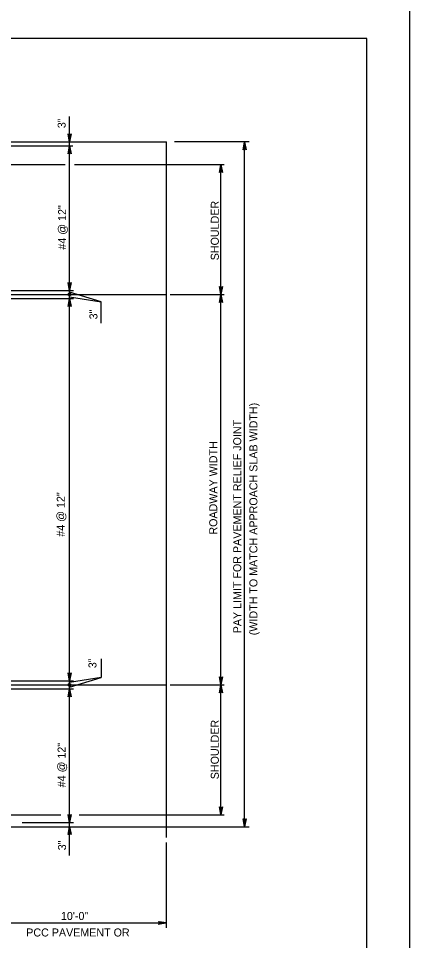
# Model space of a CAD drawing. Extents: x 2084213 to 2099800, y 976677 to 981262.
# Drawn here: x 2096353 to 2096834, y 977467 to 978601 of the extents above; entities that cross this region are included whole.
import ezdxf

# ---------------------------------------------------------------- set-up
doc = ezdxf.new("R2010")
doc.units = 0
doc.layers.add('1', color=7, linetype='Continuous')
doc.layers.add('PLT-BNDY', color=7, linetype='Continuous')

msp = doc.modelspace()

# ---------------------------------------------------------------- linework, layer by layer
at = {"layer": '1'}
for p, q in [((2096415.8, 977572.1), (2096415.8, 978480.9)), ((2095706.7, 978449.7), (2096535, 978449.7)), ((2096051.6, 978444.7), (2096420, 978444.7)), ((2096535, 977594), (2096535, 978449.7)), ((2096636.9, 978449.7), (2096545.1, 978449.7)), ((2096631.1, 977607.3), (2096631.1, 978449.7)), ((2095608.7, 978421.8), (2096410.3, 978421.8)), ((2096422, 978421.8), (2096606.1, 978421.8)), ((2096602, 978261.8), (2096602, 978421.8)), ((2095536.7, 978261.8), (2096535, 978261.8)), ((2096118.7, 978266.8), (2096420.6, 978266.8)), ((2096454.7, 978252.7), (2096415.8, 978264.8)), ((2096539.6, 978261.8), (2096606.1, 978261.8)), ((2096602, 977781.8), (2096602, 978261.8)), ((2096122.4, 978256.8), (2096420.6, 978256.8)), ((2096415.8, 978258.9), (2096454.7, 978252.7)), ((2096454.7, 978226.7), (2096454.7, 978252.7)), ((2096454.7, 977813.8), (2096454.7, 977791)), ((2096289.2, 977786.8), (2096420.6, 977786.8)), ((2096415.8, 977778.9), (2096454.7, 977791)), ((2096454.7, 977791), (2096415.8, 977784.8)), ((2095711.4, 977781.8), (2096535, 977781.8)), ((2096293.3, 977776.8), (2096420.6, 977776.8)), ((2096539.6, 977781.8), (2096606.1, 977781.8)), ((2096602, 977621.8), (2096602, 977781.8)), ((2095879.5, 977621.8), (2096405.2, 977621.8)), ((2096427.6, 977621.8), (2096606.1, 977621.8)), ((2096336.1, 977607.3), (2096427.8, 977607.3)), ((2096357.4, 977612.3), (2096420.6, 977612.3)), ((2096427.6, 977607.3), (2096636.8, 977607.3)), ((2096535, 977482.8), (2096535, 977587.8)), ((2096335, 977489), (2096535, 977489))]:
    msp.add_line(p, q, dxfattribs=at)
for points in [[(2096781.6, 976726.5), (2096781.6, 978576.9), (2094202.9, 978576.9), (2094202.9, 976726.5), (2096781.6, 976726.5), (2096781.6, 976812.9), (2096125.4, 976812.9), (2096125.4, 977025.1), (2096781.6, 977025.1), (2096781.6, 977120.2), (2096125.4, 977120.2), (2096125.4, 976726.5), (2096384, 976726.5), (2096384, 976812.9), (2096384, 976726.5), (2096636.6, 976726.5), (2096636.6, 976812.9), (2096636.6, 976772.5), (2096781.6, 976772.5)], [(2096415.8, 978449.7), (2096414, 978459.5), (2096414.2, 978459.1), (2096414.5, 978458.7), (2096414.8, 978458.5), (2096415.1, 978458.3), (2096415.5, 978458.3), (2096415.8, 978458.2), (2096416.1, 978458.3), (2096416.4, 978458.3), (2096416.8, 978458.5), (2096417.1, 978458.7), (2096417.4, 978459.1), (2096417.6, 978459.5), (2096415.8, 978449.7), (2096417.4, 978459.1), (2096417.1, 978458.7), (2096415.8, 978449.7), (2096416.8, 978458.5), (2096416.4, 978458.3), (2096415.8, 978449.7), (2096416.1, 978458.3), (2096415.8, 978458.2), (2096415.8, 978449.7), (2096415.5, 978458.3), (2096415.1, 978458.3), (2096415.8, 978449.7), (2096414.8, 978458.5), (2096414.5, 978458.7), (2096415.8, 978449.7), (2096414.2, 978459.1)], [(2096415.8, 978444.7), (2096417.6, 978434.9), (2096417.4, 978435.3), (2096417.1, 978435.7), (2096416.8, 978435.8), (2096416.4, 978436), (2096416.1, 978436.1), (2096415.8, 978436.2), (2096415.5, 978436.1), (2096415.1, 978436), (2096414.8, 978435.8), (2096414.5, 978435.7), (2096414.2, 978435.3), (2096414, 978434.9), (2096415.8, 978444.7), (2096414.2, 978435.3), (2096414.5, 978435.7), (2096415.8, 978444.7), (2096414.8, 978435.8), (2096415.1, 978436), (2096415.8, 978444.7), (2096415.5, 978436.1), (2096415.8, 978436.2), (2096415.8, 978444.7), (2096416.1, 978436.1), (2096416.4, 978436), (2096415.8, 978444.7), (2096416.8, 978435.8), (2096417.1, 978435.7), (2096415.8, 978444.7), (2096417.4, 978435.3)], [(2096631.1, 978449.7), (2096633, 978439.9), (2096632.7, 978440.3), (2096632.5, 978440.7), (2096632.1, 978440.8), (2096631.8, 978441), (2096631.5, 978441.1), (2096631.1, 978441.2), (2096630.8, 978441.1), (2096630.5, 978441), (2096630.2, 978440.8), (2096629.8, 978440.7), (2096629.6, 978440.3), (2096629.3, 978439.9), (2096631.1, 978449.7), (2096629.6, 978440.3), (2096629.8, 978440.7), (2096631.1, 978449.7), (2096630.2, 978440.8), (2096630.5, 978441), (2096631.1, 978449.7), (2096630.8, 978441.1), (2096631.1, 978441.2), (2096631.1, 978449.7), (2096631.5, 978441.1), (2096631.8, 978441), (2096631.1, 978449.7), (2096632.1, 978440.8), (2096632.5, 978440.7), (2096631.1, 978449.7), (2096632.7, 978440.3)], [(2096602, 978421.8), (2096603.9, 978412.1), (2096603.6, 978412.4), (2096603.4, 978412.8), (2096603, 978413), (2096602.7, 978413.2), (2096602.4, 978413.3), (2096602, 978413.3), (2096601.7, 978413.3), (2096601.4, 978413.2), (2096601.1, 978413), (2096600.7, 978412.8), (2096600.5, 978412.4), (2096600.2, 978412.1), (2096602, 978421.8), (2096600.5, 978412.4), (2096600.7, 978412.8), (2096602, 978421.8), (2096601.1, 978413), (2096601.4, 978413.2), (2096602, 978421.8), (2096601.7, 978413.3), (2096602, 978413.3), (2096602, 978421.8), (2096602.4, 978413.3), (2096602.7, 978413.2), (2096602, 978421.8), (2096603, 978413), (2096603.4, 978412.8), (2096602, 978421.8), (2096603.6, 978412.4)], [(2096415.8, 978266.8), (2096414, 978276.6), (2096414.2, 978276.3), (2096414.5, 978275.9), (2096414.8, 978275.7), (2096415.1, 978275.5), (2096415.5, 978275.4), (2096415.8, 978275.4), (2096416.1, 978275.4), (2096416.4, 978275.5), (2096416.8, 978275.7), (2096417.1, 978275.9), (2096417.4, 978276.3), (2096417.6, 978276.6), (2096415.8, 978266.8), (2096417.4, 978276.3), (2096417.1, 978275.9), (2096415.8, 978266.8), (2096416.8, 978275.7), (2096416.4, 978275.5), (2096415.8, 978266.8), (2096416.1, 978275.4), (2096415.8, 978275.4), (2096415.8, 978266.8), (2096415.5, 978275.4), (2096415.1, 978275.5), (2096415.8, 978266.8), (2096414.8, 978275.7), (2096414.5, 978275.9), (2096415.8, 978266.8), (2096414.2, 978276.3)], [(2096602, 978261.8), (2096600.2, 978271.6), (2096600.5, 978271.3), (2096600.7, 978270.9), (2096601.1, 978270.7), (2096601.4, 978270.5), (2096601.7, 978270.4), (2096602, 978270.4), (2096602.4, 978270.4), (2096602.7, 978270.5), (2096603, 978270.7), (2096603.4, 978270.9), (2096603.6, 978271.3), (2096603.9, 978271.6), (2096602, 978261.8), (2096603.6, 978271.3), (2096603.4, 978270.9), (2096602, 978261.8), (2096603, 978270.7), (2096602.7, 978270.5), (2096602, 978261.8), (2096602.4, 978270.4), (2096602, 978270.4), (2096602, 978261.8), (2096601.7, 978270.4), (2096601.4, 978270.5), (2096602, 978261.8), (2096601.1, 978270.7), (2096600.7, 978270.9), (2096602, 978261.8), (2096600.5, 978271.3)], [(2096602, 978261.8), (2096603.9, 978252.1), (2096603.6, 978252.4), (2096603.4, 978252.8), (2096603, 978253), (2096602.7, 978253.2), (2096602.4, 978253.3), (2096602, 978253.3), (2096601.7, 978253.3), (2096601.4, 978253.2), (2096601.1, 978253), (2096600.7, 978252.8), (2096600.5, 978252.4), (2096600.2, 978252.1), (2096602, 978261.8), (2096600.5, 978252.4), (2096600.7, 978252.8), (2096602, 978261.8), (2096601.1, 978253), (2096601.4, 978253.2), (2096602, 978261.8), (2096601.7, 978253.3), (2096602, 978253.3), (2096602, 978261.8), (2096602.4, 978253.3), (2096602.7, 978253.2), (2096602, 978261.8), (2096603, 978253), (2096603.4, 978252.8), (2096602, 978261.8), (2096603.6, 978252.4)], [(2096415.8, 978256.8), (2096417.6, 978247.1), (2096417.4, 978247.4), (2096417.1, 978247.8), (2096416.8, 978248), (2096416.4, 978248.2), (2096416.1, 978248.3), (2096415.8, 978248.3), (2096415.5, 978248.3), (2096415.1, 978248.2), (2096414.8, 978248), (2096414.5, 978247.8), (2096414.2, 978247.4), (2096414, 978247.1), (2096415.8, 978256.8), (2096414.2, 978247.4), (2096414.5, 978247.8), (2096415.8, 978256.8), (2096414.8, 978248), (2096415.1, 978248.2), (2096415.8, 978256.8), (2096415.5, 978248.3), (2096415.8, 978248.3), (2096415.8, 978256.8), (2096416.1, 978248.3), (2096416.4, 978248.2), (2096415.8, 978256.8), (2096416.8, 978248), (2096417.1, 978247.8), (2096415.8, 978256.8), (2096417.4, 978247.4)], [(2096415.8, 977786.8), (2096414, 977796.6), (2096414.2, 977796.3), (2096414.5, 977795.9), (2096414.8, 977795.7), (2096415.1, 977795.5), (2096415.5, 977795.4), (2096415.8, 977795.4), (2096416.1, 977795.4), (2096416.4, 977795.5), (2096416.8, 977795.7), (2096417.1, 977795.9), (2096417.4, 977796.3), (2096417.6, 977796.6), (2096415.8, 977786.8), (2096417.4, 977796.3), (2096417.1, 977795.9), (2096415.8, 977786.8), (2096416.8, 977795.7), (2096416.4, 977795.5), (2096415.8, 977786.8), (2096416.1, 977795.4), (2096415.8, 977795.4), (2096415.8, 977786.8), (2096415.5, 977795.4), (2096415.1, 977795.5), (2096415.8, 977786.8), (2096414.8, 977795.7), (2096414.5, 977795.9), (2096415.8, 977786.8), (2096414.2, 977796.3)], [(2096602, 977781.8), (2096600.2, 977791.6), (2096600.5, 977791.3), (2096600.7, 977790.9), (2096601.1, 977790.7), (2096601.4, 977790.5), (2096601.7, 977790.4), (2096602, 977790.4), (2096602.4, 977790.4), (2096602.7, 977790.5), (2096603, 977790.7), (2096603.4, 977790.9), (2096603.6, 977791.3), (2096603.9, 977791.6), (2096602, 977781.8), (2096603.6, 977791.3), (2096603.4, 977790.9), (2096602, 977781.8), (2096603, 977790.7), (2096602.7, 977790.5), (2096602, 977781.8), (2096602.4, 977790.4), (2096602, 977790.4), (2096602, 977781.8), (2096601.7, 977790.4), (2096601.4, 977790.5), (2096602, 977781.8), (2096601.1, 977790.7), (2096600.7, 977790.9), (2096602, 977781.8), (2096600.5, 977791.3)], [(2096415.8, 977776.8), (2096417.6, 977767.1), (2096417.4, 977767.4), (2096417.1, 977767.8), (2096416.8, 977768), (2096416.4, 977768.2), (2096416.1, 977768.3), (2096415.8, 977768.3), (2096415.5, 977768.3), (2096415.1, 977768.2), (2096414.8, 977768), (2096414.5, 977767.8), (2096414.2, 977767.4), (2096414, 977767.1), (2096415.8, 977776.8), (2096414.2, 977767.4), (2096414.5, 977767.8), (2096415.8, 977776.8), (2096414.8, 977768), (2096415.1, 977768.2), (2096415.8, 977776.8), (2096415.5, 977768.3), (2096415.8, 977768.3), (2096415.8, 977776.8), (2096416.1, 977768.3), (2096416.4, 977768.2), (2096415.8, 977776.8), (2096416.8, 977768), (2096417.1, 977767.8), (2096415.8, 977776.8), (2096417.4, 977767.4)], [(2096602, 977781.8), (2096603.9, 977772.1), (2096603.6, 977772.4), (2096603.4, 977772.8), (2096603, 977773), (2096602.7, 977773.2), (2096602.4, 977773.3), (2096602, 977773.3), (2096601.7, 977773.3), (2096601.4, 977773.2), (2096601.1, 977773), (2096600.7, 977772.8), (2096600.5, 977772.4), (2096600.2, 977772.1), (2096602, 977781.8), (2096600.5, 977772.4), (2096600.7, 977772.8), (2096602, 977781.8), (2096601.1, 977773), (2096601.4, 977773.2), (2096602, 977781.8), (2096601.7, 977773.3), (2096602, 977773.3), (2096602, 977781.8), (2096602.4, 977773.3), (2096602.7, 977773.2), (2096602, 977781.8), (2096603, 977773), (2096603.4, 977772.8), (2096602, 977781.8), (2096603.6, 977772.4)], [(2096602, 977621.8), (2096600.2, 977631.6), (2096600.5, 977631.3), (2096600.7, 977630.9), (2096601.1, 977630.7), (2096601.4, 977630.5), (2096601.7, 977630.4), (2096602, 977630.4), (2096602.4, 977630.4), (2096602.7, 977630.5), (2096603, 977630.7), (2096603.4, 977630.9), (2096603.6, 977631.3), (2096603.9, 977631.6), (2096602, 977621.8), (2096603.6, 977631.3), (2096603.4, 977630.9), (2096602, 977621.8), (2096603, 977630.7), (2096602.7, 977630.5), (2096602, 977621.8), (2096602.4, 977630.4), (2096602, 977630.4), (2096602, 977621.8), (2096601.7, 977630.4), (2096601.4, 977630.5), (2096602, 977621.8), (2096601.1, 977630.7), (2096600.7, 977630.9), (2096602, 977621.8), (2096600.5, 977631.3)], [(2096415.8, 977612.4), (2096414, 977622.2), (2096414.2, 977621.8), (2096414.5, 977621.4), (2096414.8, 977621.2), (2096415.1, 977621), (2096415.5, 977621), (2096415.8, 977620.9), (2096416.1, 977621), (2096416.4, 977621), (2096416.8, 977621.2), (2096417.1, 977621.4), (2096417.4, 977621.8), (2096417.6, 977622.2), (2096415.8, 977612.4), (2096417.4, 977621.8), (2096417.1, 977621.4), (2096415.8, 977612.4), (2096416.8, 977621.2), (2096416.4, 977621), (2096415.8, 977612.4), (2096416.1, 977621), (2096415.8, 977620.9), (2096415.8, 977612.4), (2096415.5, 977621), (2096415.1, 977621), (2096415.8, 977612.4), (2096414.8, 977621.2), (2096414.5, 977621.4), (2096415.8, 977612.4), (2096414.2, 977621.8)], [(2096631.1, 977607.3), (2096629.3, 977617.1), (2096629.6, 977616.8), (2096629.8, 977616.4), (2096630.2, 977616.2), (2096630.5, 977616), (2096630.8, 977615.9), (2096631.1, 977615.9), (2096631.5, 977615.9), (2096631.8, 977616), (2096632.1, 977616.2), (2096632.5, 977616.4), (2096632.7, 977616.8), (2096633, 977617.1), (2096631.1, 977607.3), (2096632.7, 977616.8), (2096632.5, 977616.4), (2096631.1, 977607.3), (2096632.1, 977616.2), (2096631.8, 977616), (2096631.1, 977607.3), (2096631.5, 977615.9), (2096631.1, 977615.9), (2096631.1, 977607.3), (2096630.8, 977615.9), (2096630.5, 977616), (2096631.1, 977607.3), (2096630.2, 977616.2), (2096629.8, 977616.4), (2096631.1, 977607.3), (2096629.6, 977616.8)], [(2096415.8, 977607.4), (2096417.6, 977597.6), (2096417.4, 977598), (2096417.1, 977598.3), (2096416.8, 977598.5), (2096416.4, 977598.7), (2096416.1, 977598.8), (2096415.8, 977598.8), (2096415.5, 977598.8), (2096415.1, 977598.7), (2096414.8, 977598.5), (2096414.5, 977598.3), (2096414.2, 977598), (2096414, 977597.6), (2096415.8, 977607.4), (2096414.2, 977598), (2096414.5, 977598.3), (2096415.8, 977607.4), (2096414.8, 977598.5), (2096415.1, 977598.7), (2096415.8, 977607.4), (2096415.5, 977598.8), (2096415.8, 977598.8), (2096415.8, 977607.4), (2096416.1, 977598.8), (2096416.4, 977598.7), (2096415.8, 977607.4), (2096416.8, 977598.5), (2096417.1, 977598.3), (2096415.8, 977607.4), (2096417.4, 977598)], [(2096535, 977489), (2096525.2, 977487.1), (2096525.6, 977487.4), (2096526, 977487.7), (2096526.2, 977488), (2096526.4, 977488.3), (2096526.4, 977488.6), (2096526.5, 977489), (2096526.4, 977489.3), (2096526.4, 977489.6), (2096526.2, 977490), (2096526, 977490.3), (2096525.6, 977490.5), (2096525.2, 977490.8), (2096535, 977489), (2096525.6, 977490.5), (2096526, 977490.3), (2096535, 977489), (2096526.2, 977490), (2096526.4, 977489.6), (2096535, 977489), (2096526.4, 977489.3), (2096526.5, 977489), (2096535, 977489), (2096526.4, 977488.6), (2096526.4, 977488.3), (2096535, 977489), (2096526.2, 977488), (2096526, 977487.7), (2096535, 977489), (2096525.6, 977487.4)]]:
    msp.add_lwpolyline(points, dxfattribs=at)
for centre, radius in [((2096415.8, 978261.8), 1.75), ((2096415.8, 978261.8), 0.875), ((2096415.8, 977781.8), 1.75), ((2096415.8, 977781.8), 0.875)]:
    msp.add_circle(centre, radius, dxfattribs=at)
at = {"layer": 'PLT-BNDY'}
msp.add_lwpolyline([(2094074.9, 978626.1), (2096834.1, 978626.1), (2096834.1, 976677.3), (2094074.9, 976677.3)], close=True, dxfattribs=at)

# ---------------------------------------------------------------- texts
at = {"layer": '1'}
for s, height, p in [('3"', 9.84, (2096411, 978466.5)), ('SHOULDER', 9.84, (2096599.4, 978304)), ('#4 @ 12"', 9.84, (2096411.6, 978317.1)), ('3"', 9.84, (2096450.1, 978231.3)), ('(WIDTH TO MATCH APPROACH SLAB WIDTH)', 9.843, (2096646.9, 977842.8)), ('PAY LIMIT FOR PAVEMENT RELIEF JOINT', 9.843, (2096627, 977845.2)), ('ROADWAY WIDTH', 9.843, (2096597.5, 977966.6)), ('#4 @ 12"', 9.84, (2096409.9, 977964)), ('3"', 9.84, (2096448.9, 977802.3)), ('SHOULDER', 9.84, (2096599.4, 977665.7)), ('#4 @ 12"', 9.84, (2096410.9, 977655.8)), ('3"', 9.84, (2096411.5, 977578.3))]:
    msp.add_text(s, height=height, rotation=90, dxfattribs=at).set_placement(p)
for s, height, p in [('10\'-0"', 9.84, (2096405.2, 977492.6)), ('PCC PAVEMENT OR', 9.843, (2096362.5, 977472.3))]:
    msp.add_text(s, height=height, dxfattribs=at).set_placement(p)

doc.saveas('drawing.dxf')
